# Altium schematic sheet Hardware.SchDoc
size A4; Organization: Q-Tech Design; Address1: Da Nang City; Address2: Viet Nam; DocumentNumber: 6; SheetNumber: 6; SheetTotal: 7
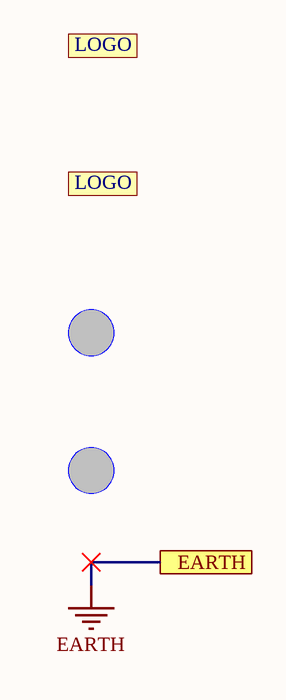
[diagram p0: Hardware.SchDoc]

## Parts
HOLE1  HOLE  [HOLE M3]  (value not drawn)
HOLE2  HOLE  [HOLE M3]  (value not drawn)
LOGO1  LOGO  [LOGO-QTECH]  (value not drawn)
LOGO2  LOGO  [LOGO-QTECH]  (value not drawn)

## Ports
EARTH

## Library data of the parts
HOLE1 HOLE2 = HOLE M3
